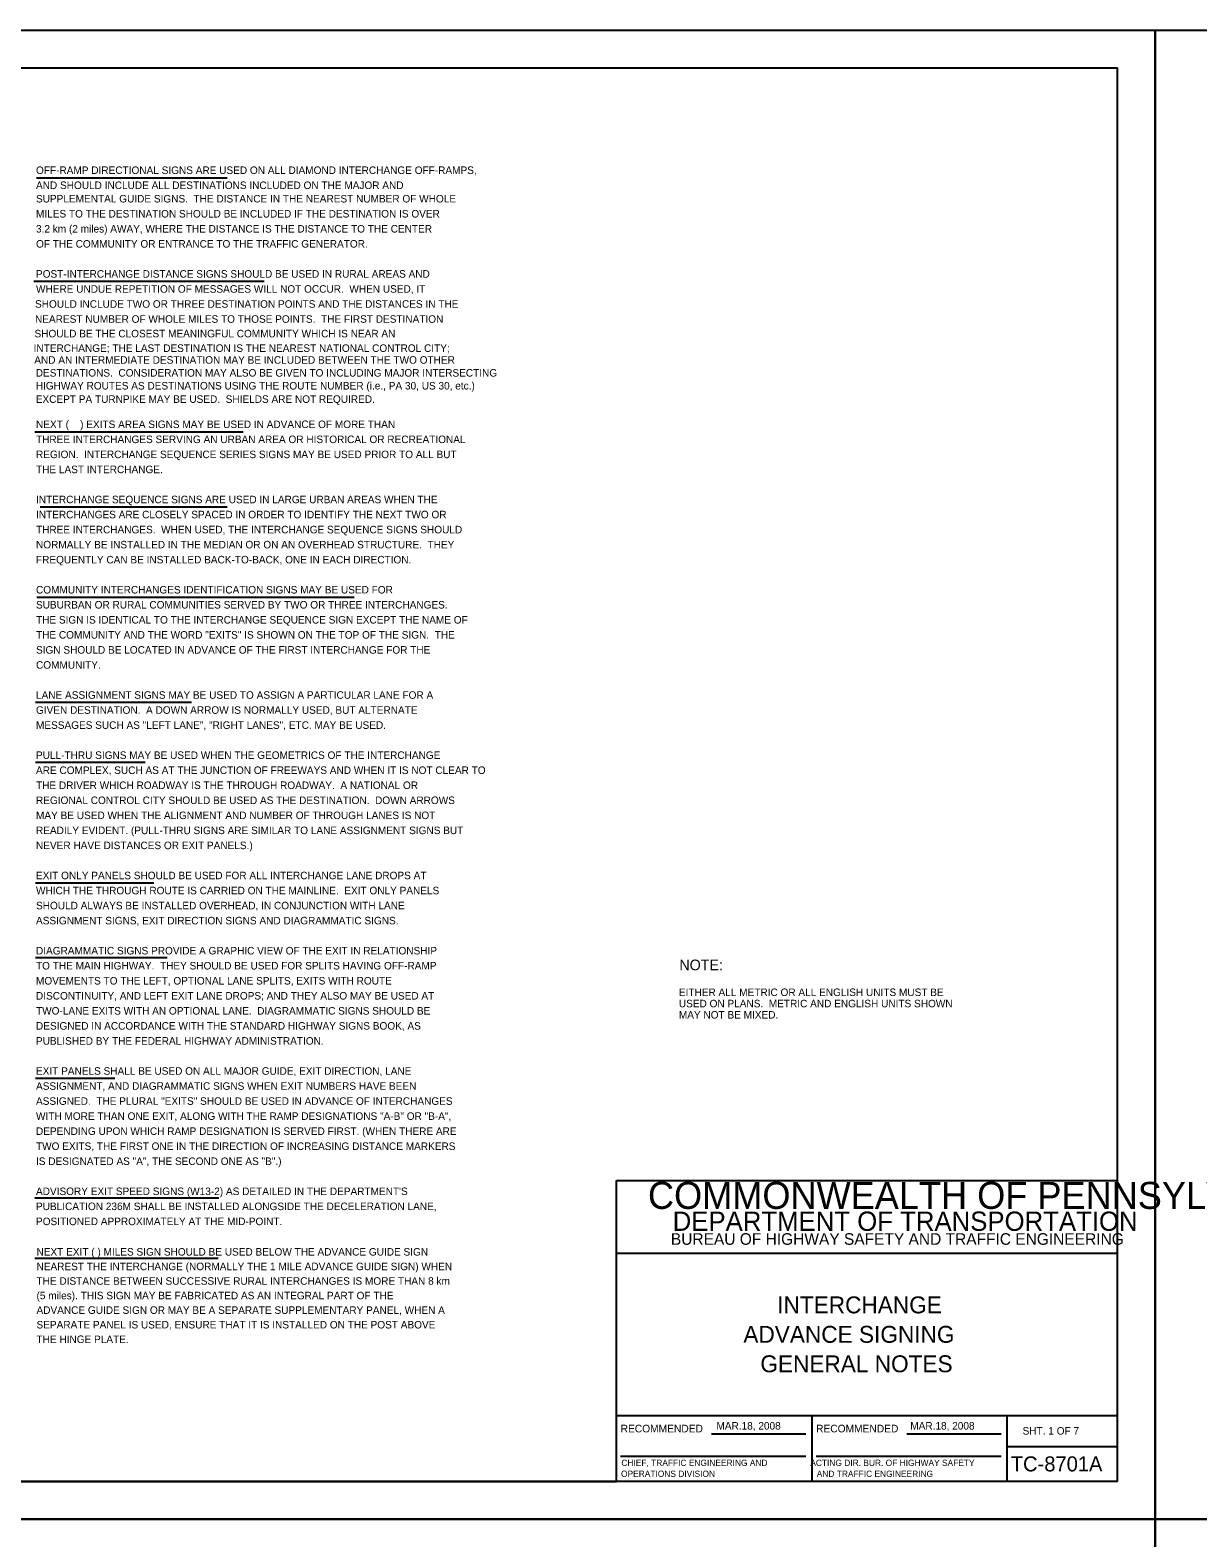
# Model space of a CAD drawing. Extents: x 640994 to 644422, y 298458 to 299646.
# Drawn here: x 641386 to 641852, y 299044 to 299646 of the extents above; entities that cross this region are included whole.
import ezdxf

# ---------------------------------------------------------------- set-up
doc = ezdxf.new("R2010")
doc.units = 0
for name, color, linetype in [('1', 7, 'Continuous'), ('2', 7, 'Continuous'), ('PLT-BNDY', 7, 'Continuous'), ('XCS-GRID-MIN', 7, 'Continuous')]:
    doc.layers.add(name, color=color, linetype=linetype)

msp = doc.modelspace()

# ---------------------------------------------------------------- linework, layer by layer
at = {"layer": '1'}
for p, q in [((641034.31, 299630.63), (641820.31, 299630.63)), ((641820.31, 299066.63), (641820.31, 299630.63)), ((641620.31, 299066.63), (641620.31, 299186.63)), ((641620.31, 299186.63), (641820.31, 299186.63)), ((641820.31, 299157.63), (641620.31, 299157.63)), ((641620.31, 299093), (641820.31, 299093)), ((641698.31, 299093), (641698.31, 299066.63)), ((641776.19, 299066.63), (641776.19, 299093)), ((641658.24, 299085.57), (641695.87, 299085.57)), ((641736.24, 299085.57), (641773.87, 299085.57)), ((641776.19, 299080.63), (641820.31, 299080.63)), ((641621.99, 299076.68), (641695.87, 299076.68)), ((641699.99, 299076.68), (641773.87, 299076.68)), ((641820.31, 299066.63), (641034.31, 299066.63)), ((641034.31, 299066.63), (641620.31, 299066.63))]:
    msp.add_line(p, q, dxfattribs=at)
at = {"layer": '2'}
for p, q in [((641388.94, 299586.75), (641464.94, 299586.75)), ((641387.81, 299545.5), (641479.69, 299545.5)), ((641388.19, 299485.38), (641471.31, 299485.38)), ((641390.31, 299455.5), (641464.94, 299455.5)), ((641389.06, 299419.38), (641515.69, 299419.38)), ((641388.44, 299377.5), (641450.69, 299377.5)), ((641388.44, 299353.63), (641432.31, 299353.63)), ((641388.44, 299305.5), (641435.69, 299305.5)), ((641388.44, 299275.63), (641441.06, 299275.63)), ((641388.44, 299227.5), (641420.19, 299227.5)), ((641388.19, 299179.75), (641461.69, 299179.75)), ((641388.19, 299155.75), (641461.32, 299155.75))]:
    msp.add_line(p, q, dxfattribs=at)
at = {"layer": 'XCS-GRID-MIN'}
for points in [[(640994.31, 299645.63), (641835.31, 299645.63), (641835.31, 299051.63), (640994.31, 299051.63)], [(641835.31, 299645.63), (642676.31, 299645.63), (642676.31, 299051.63), (641835.31, 299051.63)], [(640994.31, 299051.63), (641835.31, 299051.63), (641835.31, 298457.63), (640994.31, 298457.63)], [(641835.31, 299051.63), (642676.31, 299051.63), (642676.31, 298457.63), (641835.31, 298457.63)]]:
    msp.add_lwpolyline(points, close=True, dxfattribs=at)

# ---------------------------------------------------------------- texts
at = {"layer": '1'}
for s, height, p in [('COMMONWEALTH OF PENNSYLVANIA', 10.7828, (641632.9, 299175.36)), ('DEPARTMENT OF TRANSPORTATION', 7.6837, (641642.76, 299166.61)), ('BUREAU OF HIGHWAY SAFETY AND TRAFFIC ENGINEERING', 4.6253, (641642.04, 299161.04)), ('INTERCHANGE', 6.75, (641684.49, 299133.69)), ('ADVANCE SIGNING', 6.75, (641670.96, 299121.94)), ('GENERAL NOTES', 6.75, (641677.74, 299110.19)), ('RECOMMENDED', 3.048, (641621.99, 299086.2)), ('RECOMMENDED', 3.048, (641699.99, 299086.2)), ('SHT. 1 OF 7', 3, (641782.4, 299085.31)), ('TC-8701A', 6, (641777.68, 299070.63))]:
    msp.add_text(s, height=height, dxfattribs=at).set_placement(p)
at = {"layer": '2'}
for s, height, p in [('OFF-RAMP DIRECTIONAL SIGNS ARE USED ON ALL DIAMOND INTERCHANGE OFF-RAMPS,', 3, (641388.69, 299588.25)), ('AND SHOULD INCLUDE ALL DESTINATIONS INCLUDED ON THE MAJOR AND', 3, (641388.69, 299582.25)), ('SUPPLEMENTAL GUIDE SIGNS.  THE DISTANCE IN THE NEAREST NUMBER OF WHOLE', 3, (641388.69, 299576.88)), ('MILES TO THE DESTINATION SHOULD BE INCLUDED IF THE DESTINATION IS OVER ', 3, (641388.69, 299570.88)), ('3.2 km (2 miles) AWAY, WHERE THE DISTANCE IS THE DISTANCE TO THE CENTER ', 3, (641388.69, 299564.88)), ('OF THE COMMUNITY OR ENTRANCE TO THE TRAFFIC GENERATOR.', 3, (641388.69, 299558.88)), ('POST-INTERCHANGE DISTANCE SIGNS SHOULD BE USED IN RURAL AREAS AND', 3, (641388.69, 299546.88)), ('WHERE UNDUE REPETITION OF MESSAGES WILL NOT OCCUR.  WHEN USED, IT', 3, (641388.69, 299540.88)), ('SHOULD INCLUDE TWO OR THREE DESTINATION POINTS AND THE DISTANCES IN THE', 3, (641388.3, 299534.88)), ('NEAREST NUMBER OF WHOLE MILES TO THOSE POINTS.  THE FIRST DESTINATION', 3, (641388.3, 299528.88)), ('SHOULD BE THE CLOSEST MEANINGFUL COMMUNITY WHICH IS NEAR AN', 3, (641388.11, 299523.07)), ('INTERCHANGE; THE LAST DESTINATION IS THE NEAREST NATIONAL CONTROL CITY;', 3, (641387.73, 299517.26)), ('AND AN INTERMEDIATE DESTINATION MAY BE INCLUDED BETWEEN THE TWO OTHER', 3, (641388.01, 299512.55)), ('DESTINATIONS.  CONSIDERATION MAY ALSO BE GIVEN TO INCLUDING MAJOR INTERSECTING', 3, (641388.59, 299507.41)), ('HIGHWAY ROUTES AS DESTINATIONS USING THE ROUTE NUMBER (i.e., PA 30, US 30, etc.)', 3, (641388.59, 299502.26)), ('EXCEPT PA TURNPIKE MAY BE USED.  SHIELDS ARE NOT REQUIRED.', 3, (641388.59, 299496.93)), ('NEXT (    ) EXITS AREA SIGNS MAY BE USED IN ADVANCE OF MORE THAN', 3, (641388.69, 299486.88)), ('THREE INTERCHANGES SERVING AN URBAN AREA OR HISTORICAL OR RECREATIONAL', 3, (641388.69, 299480.88)), ('REGION.  INTERCHANGE SEQUENCE SERIES SIGNS MAY BE USED PRIOR TO ALL BUT', 3, (641388.69, 299474.88)), ('THE LAST INTERCHANGE.', 3, (641388.69, 299468.88)), ('INTERCHANGE SEQUENCE SIGNS ARE USED IN LARGE URBAN AREAS WHEN THE', 3, (641388.69, 299456.88)), ('INTERCHANGES ARE CLOSELY SPACED IN ORDER TO IDENTIFY THE NEXT TWO OR', 3, (641388.69, 299450.88)), ('THREE INTERCHANGES.  WHEN USED, THE INTERCHANGE SEQUENCE SIGNS SHOULD', 3, (641388.69, 299444.88)), ('NORMALLY BE INSTALLED IN THE MEDIAN OR ON AN OVERHEAD STRUCTURE.  THEY', 3, (641388.69, 299438.88)), ('FREQUENTLY CAN BE INSTALLED BACK-TO-BACK, ONE IN EACH DIRECTION.', 3, (641388.69, 299432.88)), ('COMMUNITY INTERCHANGES IDENTIFICATION SIGNS MAY BE USED FOR', 3, (641388.69, 299420.88)), ('SUBURBAN OR RURAL COMMUNITIES SERVED BY TWO OR THREE INTERCHANGES. ', 3, (641388.69, 299414.88)), ('THE SIGN IS IDENTICAL TO THE INTERCHANGE SEQUENCE SIGN EXCEPT THE NAME OF', 3, (641388.69, 299408.88)), ('THE COMMUNITY AND THE WORD "EXITS" IS SHOWN ON THE TOP OF THE SIGN.  THE', 3, (641388.69, 299402.88)), ('SIGN SHOULD BE LOCATED IN ADVANCE OF THE FIRST INTERCHANGE FOR THE', 3, (641388.69, 299396.88)), ('COMMUNITY.', 3, (641388.69, 299390.88)), ('LANE ASSIGNMENT SIGNS MAY BE USED TO ASSIGN A PARTICULAR LANE FOR A', 3, (641388.69, 299378.88)), ('GIVEN DESTINATION.  A DOWN ARROW IS NORMALLY USED, BUT ALTERNATE', 3, (641388.69, 299372.88)), ('MESSAGES SUCH AS "LEFT LANE", "RIGHT LANES", ETC. MAY BE USED.', 3, (641388.69, 299366.88)), ('PULL-THRU SIGNS MAY BE USED WHEN THE GEOMETRICS OF THE INTERCHANGE', 3, (641388.69, 299354.88)), ('ARE COMPLEX, SUCH AS AT THE JUNCTION OF FREEWAYS AND WHEN IT IS NOT CLEAR TO', 3, (641388.69, 299348.88)), ('THE DRIVER WHICH ROADWAY IS THE THROUGH ROADWAY.  A NATIONAL OR', 3, (641388.69, 299342.88)), ('REGIONAL CONTROL CITY SHOULD BE USED AS THE DESTINATION.  DOWN ARROWS', 3, (641388.69, 299336.88)), ('MAY BE USED WHEN THE ALIGNMENT AND NUMBER OF THROUGH LANES IS NOT', 3, (641388.69, 299330.88)), ('READILY EVIDENT. (PULL-THRU SIGNS ARE SIMILAR TO LANE ASSIGNMENT SIGNS BUT', 3, (641388.69, 299324.88)), ('NEVER HAVE DISTANCES OR EXIT PANELS.)', 3, (641388.69, 299318.88)), ('EXIT ONLY PANELS SHOULD BE USED FOR ALL INTERCHANGE LANE DROPS AT', 3, (641388.69, 299306.88)), ('WHICH THE THROUGH ROUTE IS CARRIED ON THE MAINLINE.  EXIT ONLY PANELS', 3, (641388.69, 299300.88)), ('SHOULD ALWAYS BE INSTALLED OVERHEAD, IN CONJUNCTION WITH LANE', 3, (641388.69, 299294.88)), ('ASSIGNMENT SIGNS, EXIT DIRECTION SIGNS AND DIAGRAMMATIC SIGNS.', 3, (641388.69, 299288.88)), ('DIAGRAMMATIC SIGNS PROVIDE A GRAPHIC VIEW OF THE EXIT IN RELATIONSHIP', 3, (641388.69, 299276.88)), ('TO THE MAIN HIGHWAY.  THEY SHOULD BE USED FOR SPLITS HAVING OFF-RAMP', 3, (641388.69, 299270.88)), ('NOTE:', 4.25, (641645.44, 299270.57)), ('MOVEMENTS TO THE LEFT, OPTIONAL LANE SPLITS, EXITS WITH ROUTE', 3, (641388.69, 299264.88)), ('DISCONTINUITY, AND LEFT EXIT LANE DROPS; AND THEY ALSO MAY BE USED AT', 3, (641388.69, 299258.88)), ('USED ON PLANS.  METRIC AND ENGLISH UNITS SHOWN', 3, (641645.23, 299255.79)), ('EITHER ALL METRIC OR ALL ENGLISH UNITS MUST BE', 3, (641645.23, 299260.29)), ('TWO-LANE EXITS WITH AN OPTIONAL LANE.  DIAGRAMMATIC SIGNS SHOULD BE', 3, (641388.69, 299252.88)), ('MAY NOT BE MIXED.', 3, (641645.23, 299251.29)), ('DESIGNED IN ACCORDANCE WITH THE STANDARD HIGHWAY SIGNS BOOK, AS', 3, (641388.69, 299246.88)), ('PUBLISHED BY THE FEDERAL HIGHWAY ADMINISTRATION.', 3, (641388.69, 299240.88)), ('EXIT PANELS SHALL BE USED ON ALL MAJOR GUIDE, EXIT DIRECTION, LANE', 3, (641388.69, 299228.88)), ('ASSIGNMENT, AND DIAGRAMMATIC SIGNS WHEN EXIT NUMBERS HAVE BEEN', 3, (641388.69, 299222.88)), ('ASSIGNED.  THE PLURAL "EXITS" SHOULD BE USED IN ADVANCE OF INTERCHANGES', 3, (641388.69, 299216.88)), ('WITH MORE THAN ONE EXIT, ALONG WITH THE RAMP DESIGNATIONS "A-B" OR "B-A",', 3, (641388.69, 299210.88)), ('DEPENDING UPON WHICH RAMP DESIGNATION IS SERVED FIRST. (WHEN THERE ARE', 3, (641388.69, 299204.88)), ('TWO EXITS, THE FIRST ONE IN THE DIRECTION OF INCREASING DISTANCE MARKERS', 3, (641388.69, 299198.88)), ('IS DESIGNATED AS "A", THE SECOND ONE AS "B".)', 3, (641388.69, 299192.88)), ("ADVISORY EXIT SPEED SIGNS (W13-2) AS DETAILED IN THE DEPARTMENT'S", 3, (641388.69, 299180.88)), ('PUBLICATION 236M SHALL BE INSTALLED ALONGSIDE THE DECELERATION LANE,', 3, (641388.69, 299174.88)), ('POSITIONED APPROXIMATELY AT THE MID-POINT.', 3, (641388.69, 299168.88)), ('NEXT EXIT ( ) MILES SIGN SHOULD BE USED BELOW THE ADVANCE GUIDE SIGN', 3, (641388.9, 299156.73)), ('NEAREST THE INTERCHANGE (NORMALLY THE 1 MILE ADVANCE GUIDE SIGN) WHEN', 3, (641388.9, 299150.91)), ('THE DISTANCE BETWEEN SUCCESSIVE RURAL INTERCHANGES IS MORE THAN 8 km', 3, (641388.9, 299145.1)), ('(5 miles). THIS SIGN MAY BE FABRICATED AS AN INTEGRAL PART OF THE ', 3, (641388.9, 299139.29)), ('ADVANCE GUIDE SIGN OR MAY BE A SEPARATE SUPPLEMENTARY PANEL, WHEN A ', 3, (641388.9, 299133.48)), ('SEPARATE PANEL IS USED, ENSURE THAT IT IS INSTALLED ON THE POST ABOVE ', 3, (641388.9, 299127.66)), ('THE HINGE PLATE.', 3, (641388.9, 299121.85)), ('MAR.18, 2008', 3, (641660.22, 299087.32)), ('MAR.18, 2008', 3, (641737.58, 299087.32))]:
    msp.add_text(s, height=height, dxfattribs=at).set_placement(p)
at = {"layer": 'PLT-BNDY'}
for s, p in [('CHIEF, TRAFFIC ENGINEERING AND', (641622.28, 299072.81)), ('  ACTING DIR. BUR. OF HIGHWAY SAFETY', (641695.81, 299072.8)), ('  ACTING DIR. BUR. OF HIGHWAY SAFETY', (641695.81, 299072.8)), ('OPERATIONS DIVISION', (641622.14, 299068.44))]:
    msp.add_text(s, height=2.5, dxfattribs=at).set_placement(p)
msp.add_text('AND TRAFFIC ENGINEERING', height=2.5, rotation=360, dxfattribs=at).set_placement((641700.25, 299068.43))
msp.add_text('AND TRAFFIC ENGINEERING', height=2.5, rotation=360, dxfattribs=at).set_placement((641700.25, 299068.43))

doc.saveas('drawing.dxf')
